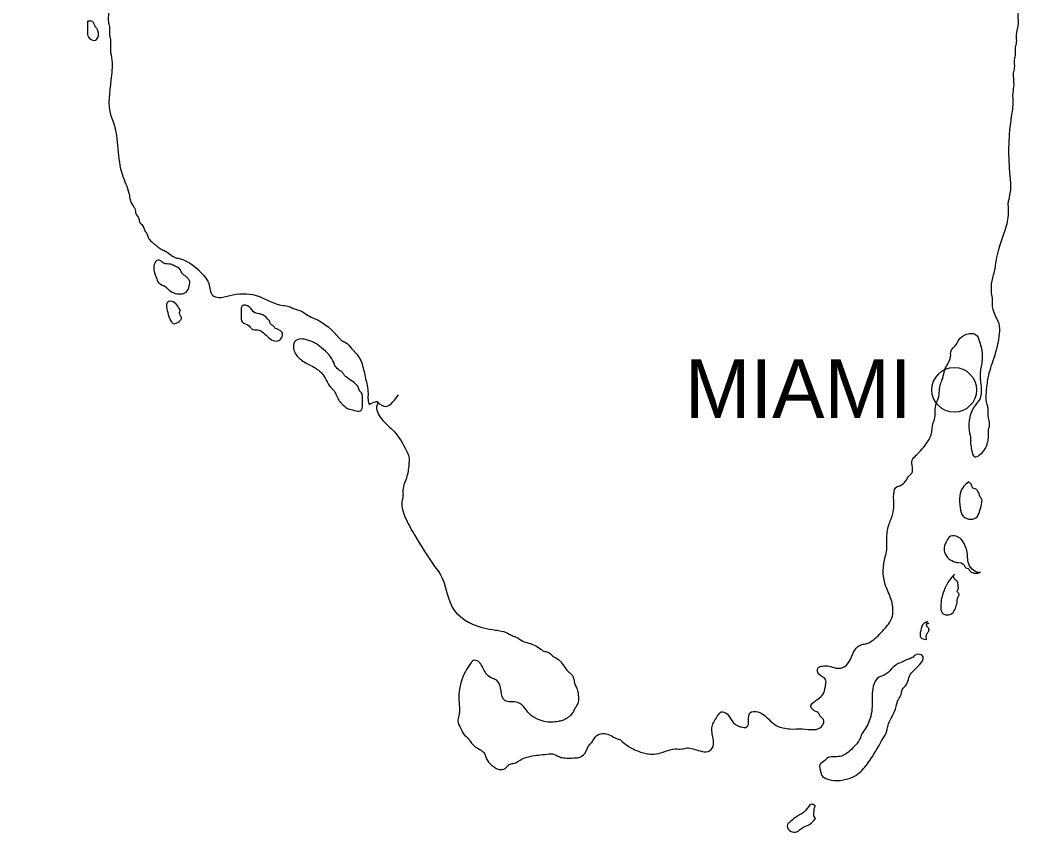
# Model space of a CAD drawing. Extents: x 565003 to 644146, y 1916234 to 1975957.
# Drawn here: x 629935 to 633003, y 1963554 to 1965994 of the extents above; entities that cross this region are included whole.
import ezdxf

# ---------------------------------------------------------------- set-up
doc = ezdxf.new("R2010")
doc.units = 0
doc.layers.add('C-TAXI-CNTR', color=7, linetype='Continuous')

msp = doc.modelspace()

# ---------------------------------------------------------------- linework, layer by layer
at = {"layer": 'C-TAXI-CNTR'}
msp.add_circle((632740.3, 1964883.9), 67.1, dxfattribs=at)
for points in [[(632774.8, 1965050.4), (632789.8, 1965053.4), (632804.8, 1965050.4), (632816.8, 1965029.4), (632824.3, 1964973.9), (632818.3, 1964934.9), (632818.3, 1964916.9), (632821.3, 1964895.9), (632821.3, 1964877.9), (632818.3, 1964858.4), (632803.3, 1964837.3), (632785.3, 1964762.3), (632789.8, 1964733.8), (632789.8, 1964721.8), (632792.8, 1964703.8), (632801.8, 1964682.8), (632816.8, 1964688.8), (632831.8, 1964703.8), (632840.8, 1964726.3), (632843.8, 1964744.3), (632843.8, 1964765.3), (632846.8, 1964777.3), (632842.3, 1964807.3), (632842.3, 1964828.3), (632839.3, 1964840.3), (632839.3, 1964898.9), (632842.3, 1964919.9), (632860.3, 1964979.9), (632876.8, 1965053.4), (632876.8, 1965074.4), (632855.8, 1965132.9), (632855.8, 1965153.9), (632852.8, 1965174.9), (632854.3, 1965210.9), (632863.3, 1965248.4), (632866.3, 1965269.4), (632893.3, 1965363.9), (632903.8, 1965414.9), (632903.8, 1965450.9), (632906.8, 1965462.9), (632906.8, 1965548.4), (632914.3, 1965714.9), (632917.3, 1965738.9), (632917.3, 1965776.4), (632920.3, 1965800.4), (632918.8, 1965836.4), (632921.8, 1965851.5), (632921.8, 1965875.5), (632924.8, 1965892), (632924.8, 1965913), (632927.8, 1965928), (632927.8, 1965949), (632933.8, 1965985), (632932.3, 1966006), (632935.3, 1966028.5), (632935.3, 1966061.5), (632944.3, 1966106.5), (632944.3, 1966121.5), (632950.4, 1966147), (632950.4, 1966177), (632953.4, 1966198), (632951.9, 1966261), (632945.8, 1966301.5), (632945.8, 1966319.5), (632935.3, 1966391.5), (632935.3, 1966426), (632932.3, 1966459), (632932.3, 1966531), (632935.3, 1966553.5), (632933.8, 1966610.5), (632936.8, 1966622.5), (632936.8, 1966661.5), (632939.8, 1966684), (632951.9, 1966702), (632972.9, 1966660), (632975.9, 1966640.5), (632981.9, 1966619.5), (632983.4, 1966598.5), (632989.4, 1966562.5), (632989.4, 1966541.5), (632992.4, 1966523.5), (632993.9, 1966390), (632990.9, 1966367.5), (632990.9, 1966325.5), (632987.9, 1966307.5), (632987.9, 1966289.5), (632984.9, 1966265.5), (632984.9, 1966253.5), (632993.9, 1966256.5), (632999.9, 1966271.5), (633002.9, 1966295.5)], [(630257.6, 1966597), (630272.6, 1966609), (630254.6, 1966585), (630248.6, 1966579), (630188.6, 1966541.5), (630170.6, 1966532.5), (630164.6, 1966520.5), (630152.6, 1966508.5), (630146.6, 1966499.5), (630137.6, 1966493.5), (630134.6, 1966483), (630095.6, 1966438), (630080.6, 1966426), (630068.6, 1966408), (630065.6, 1966388.5), (630059.6, 1966379.5), (630058.1, 1966364.5), (630049.1, 1966343.5), (630037.1, 1966331.5), (630016.1, 1966319.5), (630004.1, 1966310.5), (629983.1, 1966303), (629965.1, 1966300), (629947, 1966291), (629938, 1966267), (629935, 1966249), (629938, 1966231), (629968.1, 1966201), (629980.1, 1966195), (630028.1, 1966180), (630065.6, 1966174), (630140.6, 1966138), (630158.6, 1966123), (630179.6, 1966084), (630182.6, 1966072), (630190.1, 1966057), (630199.1, 1966007.5), (630199.1, 1965989.5), (630202.1, 1965974.5), (630202.1, 1965953.5), (630205.1, 1965935.5), (630205.1, 1965905.5), (630209.6, 1965874), (630209.6, 1965844), (630206.6, 1965813.9), (630206.6, 1965707.4), (630214.1, 1965686.4), (630241.1, 1965528.9), (630260.6, 1965474.9), (630263.6, 1965458.4), (630272.6, 1965437.4), (630278.6, 1965428.4), (630281.6, 1965413.4), (630290.6, 1965398.4), (630293.6, 1965386.4), (630299.6, 1965380.4), (630310.1, 1965359.4), (630316.1, 1965350.4), (630319.1, 1965341.4), (630343.1, 1965317.4), (630355.1, 1965308.4), (630367.1, 1965302.4), (630400.1, 1965281.4), (630412.1, 1965278.4), (630485.6, 1965227.4), (630500.6, 1965203.4), (630512.6, 1965167.4), (630530.6, 1965161.4), (630563.6, 1965167.4), (630643.1, 1965167.4), (630724.1, 1965137.4), (630742.1, 1965134.4), (630754.1, 1965128.4), (630781.1, 1965119.4), (630799.1, 1965107.4), (630818.6, 1965098.4), (630893.6, 1965038.4), (630899.6, 1965032.4), (630911.6, 1965026.4), (630929.6, 1965008.4), (630952.2, 1964981.4), (630967.2, 1964939.4), (630976.2, 1964897.4), (630979.2, 1964873.4), (630979.2, 1964853.9), (630982.2, 1964838.8)], [(630136.1, 1965991), (630136.1, 1965961), (630139.1, 1965943), (630160.1, 1965934), (630169.1, 1965946)], [(630136.1, 1965991), (630143.6, 1965992.5), (630151.1, 1965991), (630155.6, 1965983.5), (630158.6, 1965976), (630164.6, 1965968.5), (630167.6, 1965959.5), (630169.1, 1965946)], [(630386.6, 1965261.9), (630365.6, 1965264.9), (630347.6, 1965273.9), (630338.6, 1965264.9), (630335.6, 1965246.9), (630344.6, 1965216.9), (630350.6, 1965204.9), (630371.6, 1965192.9), (630377.6, 1965186.9), (630395.6, 1965174.9), (630413.6, 1965171.9), (630428.6, 1965174.9), (630440.6, 1965189.9), (630443.6, 1965210.9)], [(630443.6, 1965209.4), (630439.1, 1965216.9), (630431.6, 1965224.4), (630424.1, 1965230.4), (630418.1, 1965237.9), (630415.1, 1965245.4), (630398.6, 1965255.9), (630386.6, 1965261.9)], [(630415.1, 1965122.4), (630389.6, 1965149.4), (630380.6, 1965149.4), (630379.1, 1965110.4), (630388.1, 1965089.4), (630394.1, 1965083.4), (630412.1, 1965089.4)], [(630415.1, 1965122.4), (630412.1, 1965114.9), (630415.1, 1965107.4), (630418.1, 1965096.9), (630412.1, 1965089.4)], [(630683.6, 1965090.9), (630655.1, 1965111.9), (630640.1, 1965114.9), (630622.1, 1965132.9), (630601.1, 1965135.9), (630598.1, 1965126.9), (630598.1, 1965105.9), (630601.1, 1965087.9), (630622.1, 1965075.9), (630629.6, 1965066.9), (630647.6, 1965063.9), (630665.6, 1965054.9), (630698.6, 1965030.9), (630707.6, 1965030.9), (630719.6, 1965039.9), (630722.6, 1965054.9)], [(630722.6, 1965054.9), (630716.6, 1965060.9), (630709.1, 1965065.4), (630701.6, 1965068.4), (630694.1, 1965075.9), (630686.6, 1965081.9), (630683.6, 1965090.9)], [(630877.1, 1964964.9), (630862.1, 1964988.9), (630839.6, 1965009.9), (630818.6, 1965024.9), (630794.6, 1965033.9), (630779.6, 1965036.9), (630758.6, 1965027.9), (630755.6, 1965006.9), (630761.6, 1964991.9), (630787.1, 1964967.9), (630820.1, 1964949.9), (630844.1, 1964928.9), (630856.1, 1964907.9), (630871.1, 1964886.9), (630877.1, 1964880.9), (630893.6, 1964849.4), (630899.6, 1964843.4), (630917.6, 1964828.3), (630938.6, 1964822.3), (630956.7, 1964820.8), (630962.7, 1964838.8), (630962.7, 1964853.9), (630959.7, 1964874.9), (630953.7, 1964880.9), (630949.1, 1964892.9), (630934.1, 1964907.9), (630913.1, 1964922.9)], [(631738.2, 1963832.2), (631762.2, 1963812.7), (631789.2, 1963799.2), (631807.2, 1963793.2), (631822.2, 1963790.2), (631844.7, 1963790.2), (631901.7, 1963805.2), (631922.7, 1963805.2), (631937.7, 1963808.2), (631955.8, 1963805.2), (631976.8, 1963799.2), (632000.8, 1963797.7), (632015.8, 1963812.7), (632015.8, 1963836.7), (632012.8, 1963854.8), (632012.8, 1963872.8), (632018.8, 1963887.8), (632033.8, 1963910.3), (632039.8, 1963916.3), (632057.8, 1963910.3), (632072.8, 1963889.3), (632090.8, 1963874.3), (632099.8, 1963871.3), (632117.8, 1963871.3), (632126.8, 1963913.3), (632150.8, 1963916.3), (632168.8, 1963907.3), (632207.8, 1963874.3), (632225.8, 1963868.3), (632246.8, 1963865.3), (632284.3, 1963865.3), (632344.3, 1963875.8), (632347.3, 1963893.8), (632338.3, 1963902.8), (632333.8, 1963911.8), (632318.8, 1963920.8), (632309.8, 1963932.8), (632324.8, 1963950.8), (632345.8, 1963968.8), (632354.8, 1964003.3), (632354.8, 1964012.3), (632333.8, 1964030.3), (632330.8, 1964048.3), (632345.8, 1964054.3), (632363.8, 1964054.3), (632384.8, 1964048.3), (632399.8, 1964048.3), (632420.8, 1964061.8), (632450.8, 1964112.8), (632462.8, 1964118.8), (632477.8, 1964121.8), (632489.8, 1964127.8), (632501.8, 1964136.8), (632537.8, 1964174.3), (632546.8, 1964186.3), (632555.8, 1964210.3), (632555.8, 1964228.3), (632554.3, 1964241.8), (632551.3, 1964253.8), (632533.3, 1964298.8), (632533.3, 1964382.8), (632536.3, 1964393.3), (632537.8, 1964435.3), (632543.8, 1964477.3), (632555.8, 1964511.8), (632558.8, 1964532.8), (632558.8, 1964571.8), (632567.8, 1964592.8), (632576.8, 1964595.8), (632594.8, 1964610.8), (632606.8, 1964627.3), (632612.8, 1964633.3), (632614.3, 1964672.3), (632626.3, 1964687.3), (632632.3, 1964693.3), (632662.3, 1964730.8), (632671.3, 1964748.8), (632677.3, 1964784.8), (632683.3, 1964805.8), (632683.3, 1964820.8), (632686.3, 1964843.4), (632692.3, 1964858.4), (632699.8, 1964903.4), (632705.8, 1964918.4), (632711.8, 1964943.9), (632720.8, 1964961.9), (632729.8, 1964988.9), (632729.8, 1964997.9), (632747.8, 1965021.9), (632753.8, 1965033.9), (632774.8, 1965050.4)], [(630913.1, 1964922.9), (630907.1, 1964928.9), (630902.6, 1964936.4), (630893.6, 1964942.4), (630881.6, 1964954.4), (630875.6, 1964966.4)], [(631007.7, 1964846.4), (631033.2, 1964834.3), (631054.2, 1964847.9), (631070.7, 1964868.9)], [(630982.2, 1964840.3), (631009.2, 1964846.4), (631006.2, 1964838.8), (631007.7, 1964817.8), (631019.7, 1964796.8), (631058.7, 1964757.8), (631094.7, 1964700.8), (631102.2, 1964682.8), (631102.2, 1964664.8), (631096.2, 1964624.3), (631084.2, 1964582.3), (631084.2, 1964567.3), (631081.2, 1964546.3), (631090.2, 1964502.8), (631118.7, 1964448.8), (631180.2, 1964352.8), (631195.2, 1964331.8), (631240.2, 1964219.3), (631262.7, 1964198.3), (631280.7, 1964186.3), (631292.7, 1964180.3), (631361.7, 1964162.3), (631379.7, 1964159.3), (631403.7, 1964150.3), (631415.7, 1964144.3), (631424.7, 1964141.3), (631444.2, 1964129.3), (631462.2, 1964123.3), (631498.2, 1964105.3), (631507.2, 1964099.3), (631519.2, 1964096.3), (631534.2, 1964084.3), (631549.2, 1964075.3), (631561.2, 1964063.3), (631582.2, 1964036.3), (631589.7, 1964030.3), (631595.7, 1964021.3), (631601.7, 1963997.3), (631607.7, 1963985.3), (631610.7, 1963967.3), (631610.7, 1963946.3), (631601.7, 1963928.3), (631589.7, 1963908.8), (631562.7, 1963890.8), (631550.7, 1963887.8), (631508.7, 1963887.8), (631484.7, 1963896.8), (631469.7, 1963905.8), (631429.2, 1963944.8), (631390.2, 1963950.8), (631366.2, 1964010.8), (631354.2, 1964016.8), (631336.2, 1964028.8), (631316.7, 1964061.8), (631310.7, 1964067.8), (631295.7, 1964070.8), (631286.7, 1964061.8), (631271.7, 1964037.8), (631252.2, 1963958.3), (631252.2, 1963904.3), (631249.2, 1963889.3), (631258.2, 1963866.8), (631270.2, 1963845.8), (631280.7, 1963836.7), (631286.7, 1963827.7), (631304.7, 1963809.7), (631319.7, 1963800.7), (631328.7, 1963791.7), (631337.7, 1963770.7), (631355.7, 1963752.7), (631364.7, 1963746.7), (631382.7, 1963743.7), (631397.7, 1963752.7), (631403.7, 1963758.7), (631415.7, 1963761.7), (631442.7, 1963775.2), (631472.7, 1963784.2), (631522.2, 1963790.2), (631534.2, 1963790.2), (631555.2, 1963781.2), (631570.2, 1963778.2), (631597.2, 1963778.2), (631612.2, 1963779.7), (631630.2, 1963791.7), (631645.2, 1963818.7), (631651.2, 1963824.7), (631666.2, 1963845.8), (631690.2, 1963851.8), (631708.2, 1963845.8), (631726.2, 1963836.7), (631738.2, 1963832.2)], [(632783.8, 1964607.8), (632765.8, 1964589.8), (632756.8, 1964565.8), (632758.3, 1964529.8), (632767.3, 1964504.3), (632791.3, 1964495.3), (632809.3, 1964502.8), (632815.3, 1964514.8), (632821.3, 1964535.8), (632824.3, 1964553.8)], [(632824.3, 1964553.8), (632818.3, 1964562.8), (632810.8, 1964580.8), (632803.3, 1964586.8), (632795.8, 1964589.8), (632792.8, 1964597.3), (632782.3, 1964607.8)], [(632819.8, 1964334.8), (632804.8, 1964337.8), (632786.8, 1964355.8), (632780.8, 1964376.8), (632779.3, 1964396.3), (632773.3, 1964414.3), (632761.3, 1964435.3), (632746.3, 1964444.3), (632725.3, 1964441.3), (632719.3, 1964432.3), (632710.3, 1964409.8), (632713.3, 1964391.8), (632728.3, 1964373.8), (632749.3, 1964364.8)], [(632747.8, 1964366.3), (632770.3, 1964357.3), (632774.8, 1964349.8), (632782.3, 1964346.8), (632788.3, 1964339.3), (632803.3, 1964333.3), (632818.3, 1964334.8)], [(632741.8, 1964328.8), (632729.8, 1964316.8), (632714.8, 1964292.8), (632708.8, 1964279.3), (632699.8, 1964234.3), (632702.8, 1964216.3), (632708.8, 1964210.3), (632729.8, 1964210.3), (632747.8, 1964240.3), (632750.8, 1964261.3)], [(632750.8, 1964261.3), (632755.3, 1964270.3), (632749.3, 1964277.8), (632752.3, 1964285.3), (632752.3, 1964295.8), (632749.3, 1964309.3), (632741.8, 1964315.3), (632737.3, 1964325.8)], [(632660.8, 1964187.8), (632648.8, 1964181.8), (632639.8, 1964160.8), (632639.8, 1964139.8), (632656.3, 1964133.8)], [(632653.3, 1964184.8), (632663.8, 1964181.8), (632656.3, 1964178.8), (632660.8, 1964171.3), (632663.8, 1964163.8), (632660.8, 1964154.8), (632656.3, 1964147.3), (632656.3, 1964133.8)], [(632551.3, 1964045.3), (632530.3, 1964027.3), (632515.3, 1964021.3), (632494.3, 1963971.8), (632494.3, 1963947.8), (632485.3, 1963889.3), (632474.8, 1963868.3), (632462.8, 1963850.3), (632456.8, 1963835.2), (632435.8, 1963808.2), (632396.8, 1963782.7), (632357.8, 1963776.7), (632351.8, 1963770.7), (632336.8, 1963758.7), (632339.8, 1963734.7), (632342.8, 1963725.7), (632354.8, 1963716.7), (632423.8, 1963716.7), (632438.8, 1963722.7), (632459.8, 1963737.7), (632489.8, 1963775.2), (632525.8, 1963835.2), (632537.8, 1963859.3), (632540.8, 1963872.8), (632566.3, 1963932.8), (632572.3, 1963953.8), (632578.3, 1963962.8), (632587.3, 1963988.3), (632593.3, 1963994.3), (632611.3, 1964033.3), (632617.3, 1964039.3), (632644.3, 1964085.8), (632626.3, 1964088.8), (632617.3, 1964081.3)], [(632617.3, 1964081.3), (632605.3, 1964075.3), (632594.8, 1964072.3), (632587.3, 1964067.8), (632572.3, 1964061.8), (632564.8, 1964057.3), (632549.8, 1964043.8)], [(632306.8, 1963637.2), (632287.3, 1963614.7), (632263.3, 1963599.7), (632245.3, 1963584.7), (632239.3, 1963578.7), (632245.3, 1963560.7), (632269.3, 1963557.7), (632281.3, 1963566.7), (632305.3, 1963578.7), (632323.3, 1963596.7)], [(632306.8, 1963637.2), (632314.3, 1963640.2), (632321.8, 1963632.7), (632318.8, 1963625.2), (632318.8, 1963616.2), (632317.3, 1963608.7), (632323.3, 1963596.7)]]:
    msp.add_spline(points, degree=3, dxfattribs=at)

# ---------------------------------------------------------------- texts
msp.add_text('MIAMI', height=176.42, rotation=0, dxfattribs=at).set_placement((631931.2, 1964799.6))

doc.saveas('drawing.dxf')
